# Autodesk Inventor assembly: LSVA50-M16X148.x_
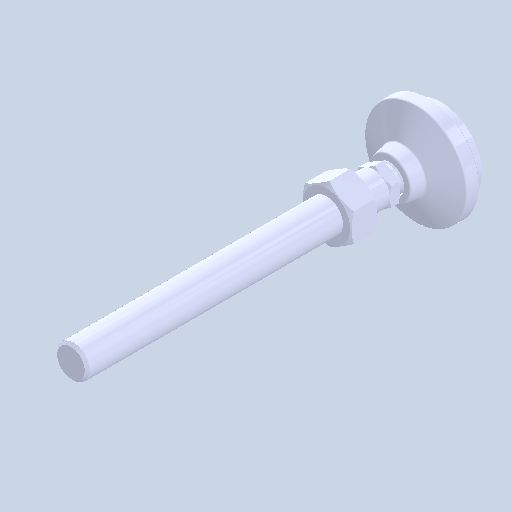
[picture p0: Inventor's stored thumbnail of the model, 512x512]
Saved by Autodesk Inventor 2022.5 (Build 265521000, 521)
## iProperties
Created: 2024-08
Part Number: LSVA50-M16X148.x_
Document SubType Name: Assembly
Designer: ImaoCorp
Author: ImaoCorp
Sending System: SOLIDWORKS 2022-2022290
MC: AMD64
MC_MODEL: Intel64 Family 6 Model 60 Stepping 3, GenuineIntel
OS: Windows_NT
FRU: Parasolid Version 33.1, build 260,  4-25-2022
FORMAT: text
GUISE: transmit
KEY: FILELSVA50-M16X148.x_t
DATE: Fri Aug 23 16:08:35 2024
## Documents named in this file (4)
- X:\14_SW2022-Inv2022\06_2024-10新製品(SME)\ELS_データ\l\lsva50-m16x148\LSVA50-M16X148.x_.iam
- X:\14_SW2022-Inv2022\06_2024-10新製品(SME)\ELS_データ\l\lsva50-m16x148\LSVA50-M16X148_01.ipt
- X:\14_SW2022-Inv2022\06_2024-10新製品(SME)\ELS_データ\l\lsva50-m16x148\LSVA50-M16X148_02.ipt
- X:\14_SW2022-Inv2022\06_2024-10新製品(SME)\ELS_データ\l\lsva50-m16x148\LSVA50-M16X148_03.ipt
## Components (3 placed, 3 different names)
1. LSVA50-M16X148_01
2. LSVA50-M16X148_02
3. LSVA50-M16X148_03
